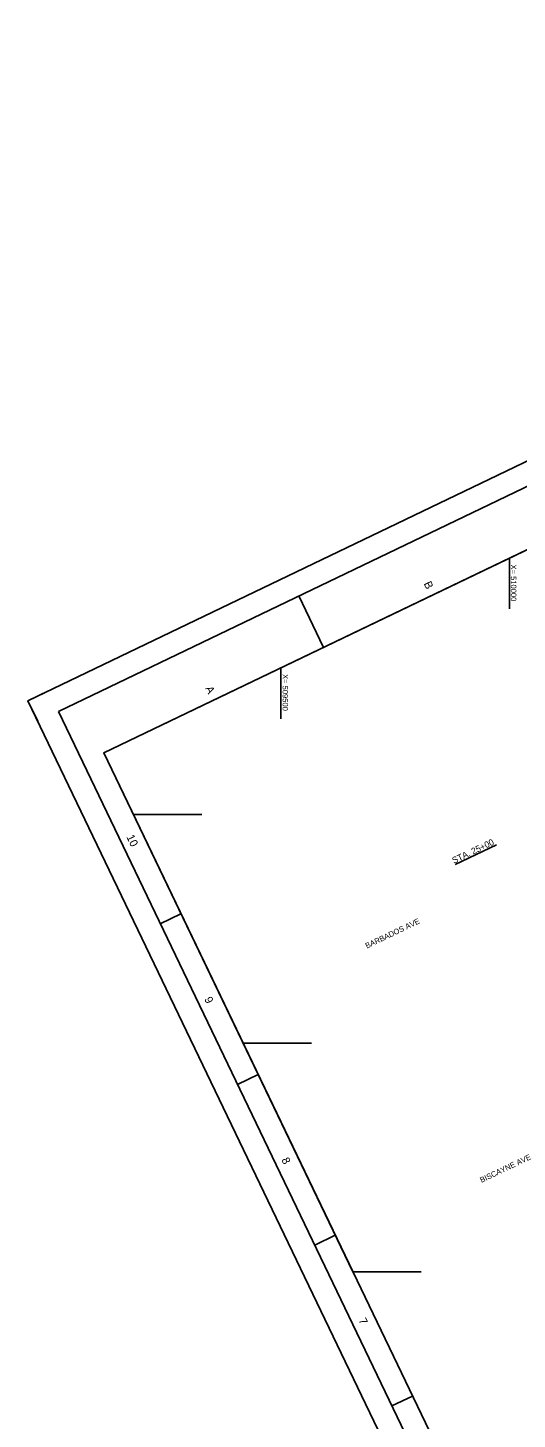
# Model space of a CAD drawing. Extents: x 508947 to 513916, y 1303283 to 1308721.
# Drawn here: x 508947 to 510017, y 1305678 to 1308721 of the extents above; entities that cross this region are included whole.
import ezdxf

# ---------------------------------------------------------------- set-up
doc = ezdxf.new("R2010")
doc.units = 0
for name, color, linetype in [('G-ANNO-NPLT', 7, 'Continuous'), ('G-ANNO-TTLB', 7, 'Continuous'), ('V-ALGN-TEXT', 7, 'Continuous'), ('V-CHAN-SYMB', 7, 'Continuous'), ('V-ROAD-IDEN', 7, 'Continuous'), ('V-TOPO-COOR-STAT', 7, 'Continuous')]:
    doc.layers.add(name, color=color, linetype=linetype)

msp = doc.modelspace()

# ---------------------------------------------------------------- linework, layer by layer
at = {"layer": 'G-ANNO-NPLT'}
msp.add_lwpolyline([(512011.7, 1308720.8), (513916.1, 1304754.3), (510851.1, 1303282.7), (508946.7, 1307249.2)], close=True, dxfattribs=at)
msp.add_lwpolyline([(508991.8, 1307270.9), (508946.7, 1307249.2), (508968.3, 1307204.2)], dxfattribs=at)
at = {"layer": 'G-ANNO-TTLB'}
for p, q in [((509539.2, 1307478.3), (509593.3, 1307365.6)), ((509236.3, 1306761.5), (509281.4, 1306783.2)), ((509405.1, 1306410), (509450.2, 1306431.6)), ((509573.9, 1306058.4), (509619, 1306080)), ((509742.7, 1305706.8), (509787.8, 1305728.5))]:
    msp.add_line(p, q, dxfattribs=at)
for points in [[(509013.4, 1307225.8), (510874.5, 1303349.5), (513849.4, 1304777.8), (511988.3, 1308654.1)], [(513782.7, 1304801.2), (511997.3, 1308519.8), (509112.6, 1307134.8), (510898, 1303416.2)]]:
    msp.add_lwpolyline(points, close=True, dxfattribs=at)
at = {"layer": 'V-ALGN-TEXT'}
msp.add_line((509971.4, 1306933.9), (509881.2, 1306890.6), dxfattribs=at)
at = {"layer": 'V-CHAN-SYMB'}
for p, q in [((511500, 1308281), (509112.6, 1307134.8)), ((509112.6, 1307134.8), (509657.4, 1306000))]:
    msp.add_line(p, q, dxfattribs=at)
at = {"layer": 'V-TOPO-COOR-STAT'}
for p, q in [((510000, 1307449.9), (510000, 1307560.8)), ((509500, 1307209.8), (509500, 1307320.8)), ((509327, 1307000), (509177.3, 1307000)), ((509567.1, 1306500), (509417.3, 1306500)), ((509807.1, 1306000), (509657.4, 1306000))]:
    msp.add_line(p, q, dxfattribs=at)

# ---------------------------------------------------------------- texts
at = {"layer": 'G-ANNO-TTLB'}
for s, p in [('B', (509811.8, 1307505.3)), ('A', (509334.4, 1307276.3)), ('10', (509161.8, 1306951.4)), ('9', (509332.1, 1306596.7)), ('8', (509500.8, 1306245.2)), ('7', (509669.4, 1305894.2))]:
    msp.add_text(s, height=17.5, rotation=295.6468, dxfattribs=at).set_placement(p)
at = {"layer": 'V-ALGN-TEXT'}
msp.add_text('STA. 25+00', height=13.92, rotation=25.6468, dxfattribs=at).set_placement((509878.5, 1306892.4))
at = {"layer": 'V-ROAD-IDEN'}
for s, p in [('BARBADOS AVE', (509688.1, 1306706.8)), ('BISCAYNE AVE', (509938.7, 1306194.5))]:
    msp.add_text(s, height=12, rotation=25.6468, dxfattribs=at).set_placement(p)
at = {"layer": 'V-TOPO-COOR-STAT'}
for s, p in [('X= 510000', (510002.9, 1307547.1)), ('X= 509500', (509503.7, 1307307.5))]:
    msp.add_text(s, height=12, rotation=270, dxfattribs=at).set_placement(p)

doc.saveas('drawing.dxf')
